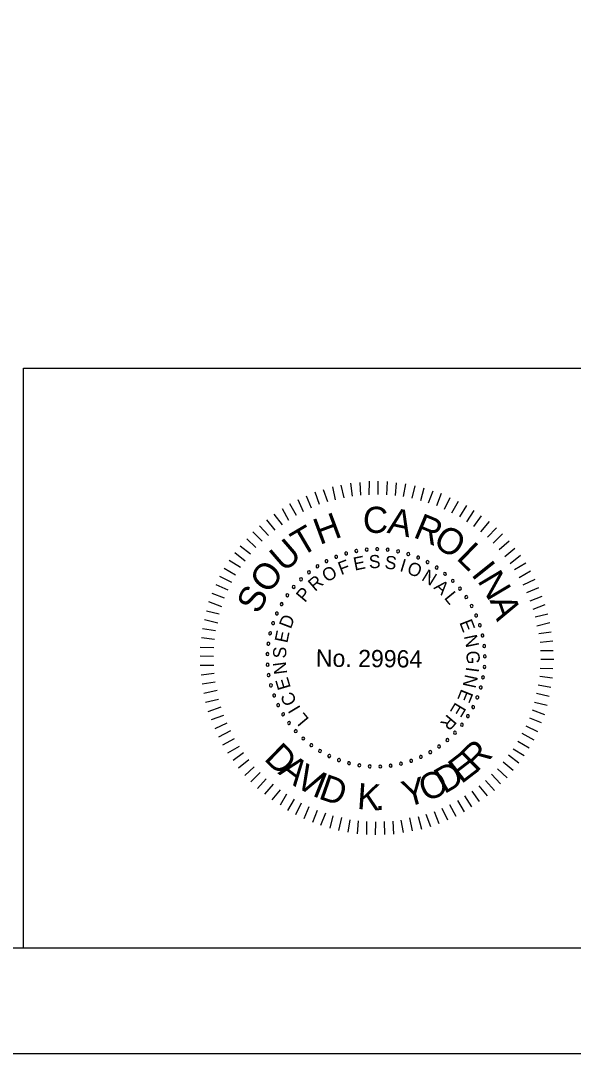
# Model space of a CAD drawing. Extents: x -133.1 to -97, y -1.7 to 20.3.
# Drawn here: x -110.52 to -107.898, y -1.691 to 3.208 of the extents above; entities that cross this region are included whole.
import ezdxf

# ---------------------------------------------------------------- set-up
doc = ezdxf.new("R2010")
doc.units = 0
for name, color, linetype in [('BR_BORDER LINES', 7, 'Continuous'), ('BR_TEXT', 7, 'Continuous'), ('Level 31', 7, 'Continuous')]:
    doc.layers.add(name, color=color, linetype=linetype)

msp = doc.modelspace()

# ---------------------------------------------------------------- linework, layer by layer
at = {"layer": 'BR_BORDER LINES'}
for p, q in [((-110.5071, 1.5591), (-105.1419, 1.5591)), ((-110.5071, -1.191), (-110.5071, 1.5591)), ((-131.3076, -1.191), (-97.6416, -1.191))]:
    msp.add_line(p, q, dxfattribs=at)
at = {"layer": 'BR_TEXT'}
for p, q in [((-109.0623, 0.9248), (-109.0842, 0.9824)), ((-109.0262, 0.9348), (-109.0394, 0.9958)), ((-108.9849, 0.9447), (-108.999, 1.0041)), ((-108.9454, 0.9521), (-108.9543, 1.0131)), ((-108.9059, 0.9561), (-108.9097, 1.017)), ((-108.8664, 0.9584), (-108.8658, 1.0227)), ((-108.8243, 0.9606), (-108.8238, 1.0224)), ((-108.7823, 0.9577), (-108.78, 1.022)), ((-108.742, 0.9548), (-108.7372, 1.0156)), ((-108.7034, 0.9501), (-108.6926, 1.011)), ((-108.6631, 0.9421), (-108.6489, 1.0012)), ((-108.622, 0.9314), (-108.606, 0.9922)), ((-109.1777, 0.8785), (-109.2039, 0.9345)), ((-109.1406, 0.8954), (-109.1642, 0.9514)), ((-109.1019, 0.9122), (-109.1229, 0.9708)), ((-108.5852, 0.9208), (-108.5633, 0.9781)), ((-108.5458, 0.9076), (-108.5239, 0.9658)), ((-108.5099, 0.8902), (-108.482, 0.9457)), ((-109.2475, 0.8371), (-109.278, 0.8914)), ((-109.2122, 0.8608), (-109.2426, 0.9151)), ((-108.474, 0.8727), (-108.4427, 0.9282)), ((-108.4364, 0.8544), (-108.4042, 0.9082)), ((-108.4031, 0.8301), (-108.3692, 0.8839)), ((-109.3123, 0.7904), (-109.3522, 0.8405)), ((-109.2786, 0.8159), (-109.3177, 0.8668)), ((-108.3699, 0.8083), (-108.3334, 0.8587)), ((-109.3451, 0.7658), (-109.3868, 0.8107)), ((-108.3375, 0.7824), (-108.2968, 0.8318)), ((-108.3059, 0.7572), (-108.2627, 0.8014)), ((-109.4039, 0.7079), (-109.4474, 0.7503)), ((-109.3745, 0.7386), (-109.4188, 0.7827)), ((-108.2779, 0.7295), (-108.2346, 0.7729)), ((-108.2498, 0.6984), (-108.2022, 0.74)), ((-109.4291, 0.6763), (-109.4786, 0.7154)), ((-108.2226, 0.6664), (-108.1759, 0.7046)), ((-109.4768, 0.6141), (-109.5306, 0.6472)), ((-109.4551, 0.6431), (-109.5046, 0.683)), ((-108.1988, 0.6327), (-108.1496, 0.6718)), ((-109.5012, 0.5774), (-109.5549, 0.6096)), ((-108.1768, 0.6034), (-108.1242, 0.6355)), ((-108.1548, 0.5663), (-108.1013, 0.5976)), ((-109.5186, 0.5432), (-109.575, 0.5711)), ((-108.137, 0.5318), (-108.0793, 0.5588)), ((-109.5536, 0.468), (-109.6117, 0.4899)), ((-109.5361, 0.5065), (-109.5933, 0.5318)), ((-108.1193, 0.4948), (-108.0624, 0.5192)), ((-109.5659, 0.4278), (-109.6275, 0.4506)), ((-108.1025, 0.456), (-108.0456, 0.477)), ((-109.5782, 0.3918), (-109.639, 0.4069)), ((-108.0891, 0.4156), (-108.0314, 0.4374)), ((-108.079, 0.3794), (-108.0189, 0.3935)), ((-109.5854, 0.3498), (-109.6479, 0.3658)), ((-108.0708, 0.3373), (-108.0106, 0.3522)), ((-109.596, 0.3138), (-109.6569, 0.3221)), ((-108.0625, 0.3012), (-108.0033, 0.3084)), ((-109.6006, 0.2727), (-109.6624, 0.2801)), ((-108.056, 0.26), (-107.995, 0.2663)), ((-109.6035, 0.2333), (-109.6679, 0.2338)), ((-108.0546, 0.2205), (-107.9945, 0.22)), ((-109.6042, 0.1492), (-109.6686, 0.148)), ((-109.6056, 0.1921), (-109.6682, 0.1926)), ((-108.0524, 0.1793), (-107.9915, 0.1788)), ((-109.602, 0.1105), (-109.6638, 0.1033)), ((-108.0553, 0.1364), (-107.9952, 0.1342)), ((-109.598, 0.0693), (-109.659, 0.0604)), ((-108.0645, 0.0566), (-108.0054, 0.0467)), ((-108.0574, 0.0978), (-107.9965, 0.0896)), ((-109.5881, 0.0297), (-109.6508, 0.0165)), ((-108.0735, 0.0172), (-108.0135, 0.003)), ((-109.5815, -0.0124), (-109.6426, -0.0265)), ((-108.0824, -0.0248), (-108.0224, -0.0398)), ((-109.5698, -0.0493), (-109.6318, -0.0703)), ((-109.5582, -0.0881), (-109.6167, -0.1091)), ((-108.093, -0.0615), (-108.0357, -0.0835)), ((-109.5413, -0.1251), (-109.599, -0.1521)), ((-108.1245, -0.1368), (-108.0681, -0.1647)), ((-108.107, -0.1001), (-108.0506, -0.122)), ((-109.5244, -0.1613), (-109.5813, -0.1909)), ((-108.1428, -0.1727), (-108.0856, -0.2032)), ((-109.5076, -0.1984), (-109.5619, -0.2297)), ((-109.4838, -0.2355), (-109.5382, -0.2668)), ((-108.1612, -0.2095), (-108.1082, -0.2417)), ((-109.4626, -0.2648), (-109.5127, -0.3013)), ((-108.2063, -0.2752), (-108.1577, -0.3125)), ((-108.1838, -0.2462), (-108.1317, -0.2784)), ((-109.4372, -0.2985), (-109.4873, -0.3376)), ((-109.4125, -0.3321), (-109.4567, -0.373)), ((-108.2583, -0.3417), (-108.2115, -0.3833)), ((-108.2306, -0.3084), (-108.1846, -0.3483)), ((-109.3836, -0.3582), (-109.4286, -0.4032)), ((-109.3547, -0.3884), (-109.3971, -0.4344)), ((-108.2869, -0.3672), (-108.2444, -0.413)), ((-109.3222, -0.4144), (-109.363, -0.4613)), ((-109.289, -0.4404), (-109.3289, -0.4882)), ((-108.3474, -0.4225), (-108.3075, -0.47)), ((-108.3155, -0.397), (-108.273, -0.4437)), ((-109.2583, -0.4622), (-109.2896, -0.5142)), ((-109.2233, -0.4847), (-109.2546, -0.5386)), ((-108.4139, -0.4691), (-108.3808, -0.5217)), ((-108.3802, -0.448), (-108.3446, -0.4963)), ((-109.1891, -0.5048), (-109.2162, -0.5603)), ((-109.1523, -0.5222), (-109.1769, -0.5778)), ((-108.5216, -0.5274), (-108.4947, -0.5835)), ((-108.4855, -0.5106), (-108.455, -0.5666)), ((-108.4475, -0.4911), (-108.4162, -0.5455)), ((-109.1139, -0.5397), (-109.1358, -0.5962)), ((-109.0745, -0.552), (-109.0973, -0.6102)), ((-109.0386, -0.5644), (-109.0528, -0.6235)), ((-108.9974, -0.5716), (-109.0126, -0.6333)), ((-108.9581, -0.5831), (-108.968, -0.6413)), ((-108.9186, -0.5877), (-108.9234, -0.6494)), ((-108.7161, -0.5851), (-108.7062, -0.6435)), ((-108.6756, -0.5742), (-108.6624, -0.6361)), ((-108.6344, -0.5677), (-108.6194, -0.627)), ((-108.5974, -0.556), (-108.5764, -0.6145)), ((-108.5578, -0.5443), (-108.5368, -0.6011)), ((-108.8792, -0.5906), (-108.8797, -0.6524)), ((-108.8372, -0.5935), (-108.8377, -0.6544)), ((-108.7951, -0.5913), (-108.7939, -0.6531)), ((-108.7547, -0.589), (-108.7509, -0.6509))]:
    msp.add_line(p, q, dxfattribs=at)
for centre, start, end in [((-108.9763, 0.6806), 16.1422, 196.1422), ((-108.9278, 0.692), 10.6038, 190.6038), ((-108.9278, 0.692), 190.6038, 10.6038), ((-108.8784, 0.6987), 5.0653, 185.0653), ((-108.8784, 0.6987), 185.0653, 5.0653), ((-108.8286, 0.7006), 359.5268, 179.5268), ((-108.8286, 0.7006), 179.5268, 359.5268), ((-108.7789, 0.6977), 173.9884, 353.9884), ((-108.7789, 0.6977), 353.9884, 173.9884), ((-108.7296, 0.69), 168.4499, 348.4499), ((-108.7296, 0.69), 348.4499, 168.4499), ((-109.0689, 0.644), 27.2191, 207.2191), ((-109.0689, 0.644), 207.2191, 27.2191), ((-109.0235, 0.6646), 21.6807, 201.6807), ((-109.0235, 0.6646), 201.6807, 21.6807), ((-108.9763, 0.6806), 196.1422, 16.1422), ((-108.6814, 0.6776), 162.9114, 342.9114), ((-108.6814, 0.6776), 342.9114, 162.9114), ((-108.6345, 0.6606), 157.373, 337.373), ((-108.6345, 0.6606), 337.373, 157.373), ((-108.5896, 0.6391), 151.8345, 331.8345), ((-108.5896, 0.6391), 331.8345, 151.8345), ((-109.1527, 0.5903), 38.2961, 218.2961), ((-109.1527, 0.5903), 218.2961, 38.2961), ((-109.1121, 0.6192), 32.7576, 212.7576), ((-109.1121, 0.6192), 212.7576, 32.7576), ((-108.5469, 0.6134), 146.2961, 326.2961), ((-108.5469, 0.6134), 326.2961, 146.2961), ((-108.5069, 0.5837), 140.7576, 320.7576), ((-108.5069, 0.5837), 320.7576, 140.7576), ((-109.1903, 0.5577), 43.8345, 223.8345), ((-109.1903, 0.5577), 223.8345, 43.8345), ((-108.4699, 0.5503), 135.2191, 315.2191), ((-108.4699, 0.5503), 315.2191, 135.2191), ((-109.2246, 0.5215), 49.373, 229.373), ((-109.2246, 0.5215), 229.373, 49.373), ((-108.4363, 0.5134), 129.6807, 309.6807), ((-108.4363, 0.5134), 309.6807, 129.6807), ((-109.282, 0.4402), 60.4499, 240.4499), ((-109.282, 0.4402), 240.4499, 60.4499), ((-109.2553, 0.4822), 54.9114, 234.9114), ((-109.2553, 0.4822), 234.9114, 54.9114), ((-108.4065, 0.4735), 124.1422, 304.1422), ((-108.4065, 0.4735), 304.1422, 124.1422), ((-109.3045, 0.3957), 65.9884, 245.9884), ((-109.3045, 0.3957), 245.9884, 65.9884), ((-108.3806, 0.4309), 118.6038, 298.6038), ((-108.3806, 0.4309), 298.6038, 118.6038), ((-108.359, 0.3861), 113.0653, 293.0653), ((-108.359, 0.3861), 293.0653, 113.0653), ((-109.3227, 0.3493), 71.5268, 251.5268), ((-109.3227, 0.3493), 251.5268, 71.5268), ((-108.3418, 0.3393), 107.5268, 287.5268), ((-108.3418, 0.3393), 287.5268, 107.5268), ((-109.3363, 0.3014), 77.0653, 257.0653), ((-109.3363, 0.3014), 257.0653, 77.0653), ((-108.3292, 0.2911), 101.9884, 281.9884), ((-108.3292, 0.2911), 281.9884, 101.9884), ((-109.3452, 0.2524), 82.6038, 262.6038), ((-109.3452, 0.2524), 262.6038, 82.6038), ((-108.3213, 0.2419), 96.4499, 276.4499), ((-108.3213, 0.2419), 276.4499, 96.4499), ((-109.3493, 0.2027), 88.1422, 268.1422), ((-109.3493, 0.2027), 268.1422, 88.1422), ((-108.3182, 0.1921), 90.9114, 270.9114), ((-108.3182, 0.1921), 270.9114, 90.9114), ((-109.3486, 0.1529), 93.6807, 273.6807), ((-109.3486, 0.1529), 273.6807, 93.6807), ((-108.3199, 0.1423), 85.373, 265.373), ((-108.3199, 0.1423), 265.373, 85.373), ((-109.3431, 0.1033), 99.2191, 279.2191), ((-109.3431, 0.1033), 279.2191, 99.2191), ((-108.3265, 0.0929), 79.8345, 259.8345), ((-108.3265, 0.0929), 259.8345, 79.8345), ((-109.3328, 0.0546), 104.7576, 284.7576), ((-109.3328, 0.0546), 284.7576, 104.7576), ((-108.3377, 0.0444), 74.2961, 254.2961), ((-108.3377, 0.0444), 254.2961, 74.2961), ((-109.3179, 0.007), 110.2961, 290.2961), ((-109.3179, 0.007), 290.2961, 110.2961), ((-108.3536, -0.0028), 68.7576, 248.7576), ((-108.3536, -0.0028), 248.7576, 68.7576), ((-109.2985, -0.0389), 115.8345, 295.8345), ((-109.2985, -0.0389), 295.8345, 115.8345), ((-108.374, -0.0483), 63.2191, 243.2191), ((-108.374, -0.0483), 243.2191, 63.2191), ((-109.2747, -0.0826), 121.373, 301.373), ((-109.2747, -0.0826), 301.373, 121.373), ((-108.3986, -0.0916), 57.6807, 237.6807), ((-108.3986, -0.0916), 237.6807, 57.6807), ((-109.2468, -0.1239), 126.9114, 306.9114), ((-109.2468, -0.1239), 306.9114, 126.9114), ((-108.4273, -0.1323), 52.1422, 232.1422), ((-108.4273, -0.1323), 232.1422, 52.1422), ((-109.2151, -0.1624), 132.4499, 312.4499), ((-109.2151, -0.1624), 312.4499, 132.4499), ((-109.1798, -0.1975), 137.9884, 317.9884), ((-109.1798, -0.1975), 317.9884, 137.9884), ((-108.4599, -0.1701), 46.6038, 226.6038), ((-108.4599, -0.1701), 226.6038, 46.6038), ((-109.1413, -0.2291), 143.5268, 323.5268), ((-109.1413, -0.2291), 323.5268, 143.5268), ((-108.5351, -0.2353), 35.5268, 215.5268), ((-108.5351, -0.2353), 215.5268, 35.5268), ((-108.4959, -0.2045), 41.0653, 221.0653), ((-108.4959, -0.2045), 221.0653, 41.0653), ((-109.0999, -0.2569), 149.0653, 329.0653), ((-109.0999, -0.2569), 329.0653, 149.0653), ((-109.056, -0.2805), 154.6038, 334.6038), ((-109.056, -0.2805), 334.6038, 154.6038), ((-109.01, -0.2997), 340.1422, 160.1422), ((-108.6214, -0.2849), 24.4499, 204.4499), ((-108.6214, -0.2849), 204.4499, 24.4499), ((-108.577, -0.2622), 29.9884, 209.9884), ((-108.577, -0.2622), 209.9884, 29.9884), ((-109.01, -0.2997), 160.1422, 340.1422), ((-108.9624, -0.3145), 165.6807, 345.6807), ((-108.9624, -0.3145), 345.6807, 165.6807), ((-108.9136, -0.3245), 171.2191, 351.2191), ((-108.9136, -0.3245), 351.2191, 171.2191), ((-108.8641, -0.3299), 356.7576, 176.7576), ((-108.8641, -0.3299), 176.7576, 356.7576), ((-108.8142, -0.3304), 2.2961, 182.2961), ((-108.8142, -0.3304), 182.2961, 2.2961), ((-108.7646, -0.3261), 7.8345, 187.8345), ((-108.7646, -0.3261), 187.8345, 7.8345), ((-108.7156, -0.317), 13.373, 193.373), ((-108.7156, -0.317), 193.373, 13.373), ((-108.6677, -0.3032), 18.9114, 198.9114), ((-108.6677, -0.3032), 198.9114, 18.9114)]:
    msp.add_arc(centre, 0.00701, start, end, dxfattribs=at)
at = {"layer": 'Level 31'}
msp.add_lwpolyline([(-133.1409, -1.691), (-97.141, -1.691), (-97.141, 20.309), (-133.1409, 20.309)], close=True, dxfattribs=at)

# ---------------------------------------------------------------- texts
at = {"layer": 'BR_TEXT'}
for s, height, rotation, p in [('C', 0.1241, 359.5482, (-108.8971, 0.7782)), ('A', 0.1241, 348.1981, (-108.7857, 0.779)), ('H', 0.1241, 20.3637, (-109.1015, 0.7199)), ('R', 0.1241, 337.4344, (-108.6624, 0.7591)), ('T', 0.1241, 30.4992, (-109.1894, 0.6624)), ('O', 0.1239, 326.5869, (-108.5702, 0.7224)), ('U', 0.1241, 40.8022, (-109.2706, 0.5876)), ('L', 0.1241, 315.9488, (-108.4576, 0.6546)), ('F', 0.0622, 20.6127, (-109.0002, 0.577)), ('E', 0.0622, 11.4103, (-108.9351, 0.5987)), ('S', 0.0622, 2.208, (-108.8672, 0.6097)), ('S', 0.0622, 352.6608, (-108.796, 0.6095)), ('I', 0.0622, 343.1136, (-108.7257, 0.5975)), ('O', 0.0622, 338.4392, (-108.6923, 0.5873)), ('I', 0.1241, 308.6613, (-108.3862, 0.5803)), ('O', 0.1241, 52.0267, (-109.3451, 0.4837)), ('O', 0.0622, 30.8477, (-109.0676, 0.541)), ('N', 0.0622, 328.2042, (-108.6227, 0.5559)), ('N', 0.1241, 300.7037, (-108.3556, 0.5509)), ('R', 0.0622, 40.3949, (-109.1237, 0.4971)), ('A', 0.0622, 318.657, (-108.5637, 0.5159)), ('S', 0.1239, 63.2511, (-109.3905, 0.3881)), ('P', 0.0622, 49.9421, (-109.1718, 0.4445)), ('L', 0.0622, 309.4546, (-108.5139, 0.4686)), ('A', 0.1241, 289.4792, (-108.2964, 0.4579)), ('D', 0.0622, 69.0364, (-109.2388, 0.3192)), ('E', 0.0622, 291.049, (-108.44, 0.3533)), ('E', 0.0622, 78.2388, (-109.2553, 0.2526)), ('N', 0.0622, 281.8466, (-108.4179, 0.2882)), ('S', 0.0622, 87.786, (-109.2611, 0.1815)), ('No. 29964', 0.08175, 359.5268, (-109.1199, 0.1431)), ('G', 0.0622, 272.2995, (-108.4061, 0.2179)), ('N', 0.0622, 97.3332, (-109.2549, 0.1105)), ('N', 0.0622, 257.7339, (-108.411, 0.1095)), ('I', 0.0622, 262.4084, (-108.4065, 0.1441)), ('E', 0.0622, 106.5355, (-109.2379, 0.044)), ('C', 0.0622, 116.4266, (-109.208, -0.0235)), ('E', 0.0622, 248.1867, (-108.4291, 0.0406)), ('I', 0.0622, 121.1011, (-109.1899, -0.0534)), ('E', 0.0622, 238.9844, (-108.457, -0.0222)), ('L', 0.0622, 129.9595, (-109.1493, -0.1056)), ('R', 0.0622, 229.782, (-108.4947, -0.0797)), ('D', 0.1236, 315.4053, (-109.3698, -0.2962)), ('R', 0.1236, 44.5947, (-108.3589, -0.3617)), ('A', 0.1236, 322.8377, (-109.3032, -0.3618)), ('E', 0.1236, 37.5339, (-108.4295, -0.4156)), ('V', 0.1236, 330.5179, (-109.226, -0.42)), ('D', 0.1236, 30.1015, (-108.5104, -0.4626)), ('I', 0.1236, 338.1981, (-109.1418, -0.4674)), ('D', 0.1236, 340.7995, (-109.1119, -0.4808)), ('Y', 0.1236, 14.8649, (-108.6915, -0.5241)), ('O', 0.1236, 22.4212, (-108.5997, -0.4996)), ('K', 0.1236, 356.098, (-108.9267, -0.5314)), ('.', 0.1236, 3.1588, (-108.838, -0.5377))]:
    msp.add_text(s, height=height, rotation=rotation, dxfattribs=at).set_placement(p)

doc.saveas('drawing.dxf')
